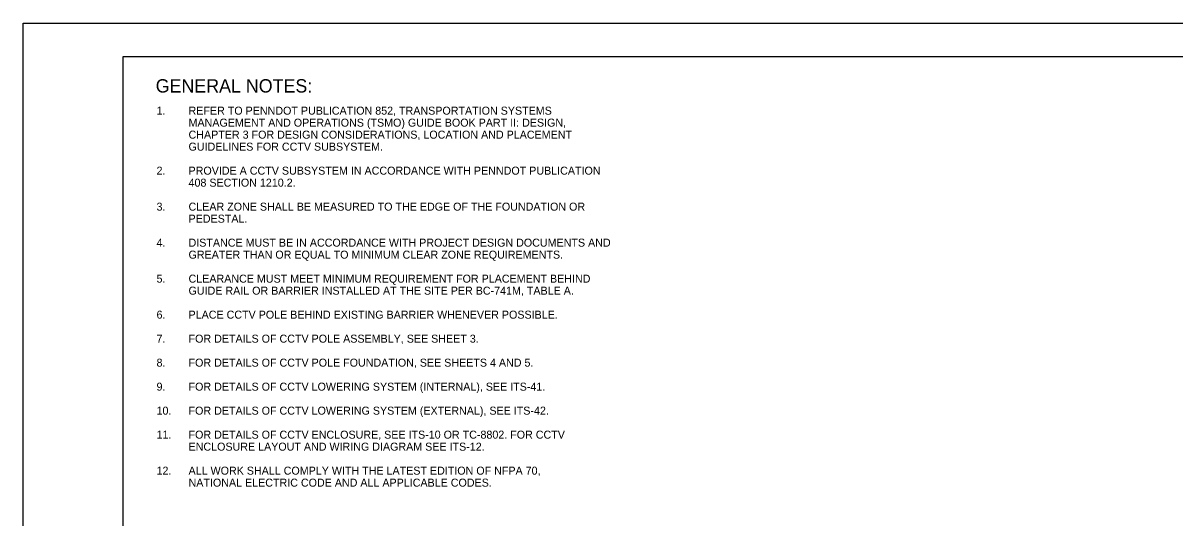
# Model space of a CAD drawing. Extents: x 1299104.8 to 1299141.6, y 239639.8 to 239661.8.
# Drawn here: x 1299104.8 to 1299122.08, y 239654.37 to 239661.79 of the extents above; entities that cross this region are included whole.
import ezdxf

# ---------------------------------------------------------------- set-up
doc = ezdxf.new("R2010")
doc.units = 0
for name, color, linetype in [('DIM TXT', 7, 'Continuous'), ('GS_plotshape_p', 7, 'Continuous'), ('Level 1', 7, 'Continuous')]:
    doc.layers.add(name, color=color, linetype=linetype)

msp = doc.modelspace()

# ---------------------------------------------------------------- linework, layer by layer
at = {"layer": 'DIM TXT'}
msp.add_line((1299104.802, 239661.791), (1299104.802, 239661.791), dxfattribs=at)
at = {"layer": 'GS_plotshape_p'}
msp.add_lwpolyline([(1299104.802, 239661.791), (1299138.802, 239661.791), (1299138.802, 239639.791), (1299104.802, 239639.791)], close=True, dxfattribs=at)
at = {"layer": 'Level 1'}
msp.add_lwpolyline([(1299138.302, 239640.291), (1299106.302, 239640.291), (1299106.302, 239661.291), (1299138.302, 239661.291)], close=True, dxfattribs=at)

# ---------------------------------------------------------------- texts
at = {"layer": 'DIM TXT'}
for s, height, p in [('GENERAL NOTES:', 0.2, (1299106.791, 239660.749)), ('1.', 0.12, (1299106.804, 239660.417)), ('REFER TO PENNDOT PUBLICATION 852, TRANSPORTATION SYSTEMS ', 0.12, (1299107.284, 239660.417)), ('MANAGEMENT AND OPERATIONS (TSMO) GUIDE BOOK PART II: DESIGN, ', 0.12, (1299107.284, 239660.237)), ('CHAPTER 3 FOR DESIGN CONSIDERATIONS, LOCATION AND PLACEMENT ', 0.12, (1299107.284, 239660.057)), ('GUIDELINES FOR CCTV SUBSYSTEM.', 0.12, (1299107.284, 239659.877)), ('2.', 0.12, (1299106.804, 239659.517)), ('PROVIDE A CCTV SUBSYSTEM IN ACCORDANCE WITH PENNDOT PUBLICATION ', 0.12, (1299107.284, 239659.517)), ('408 SECTION 1210.2.', 0.12, (1299107.284, 239659.337)), ('3.', 0.12, (1299106.804, 239658.977)), ('CLEAR ZONE SHALL BE MEASURED TO THE EDGE OF THE FOUNDATION OR ', 0.12, (1299107.284, 239658.977)), ('PEDESTAL.', 0.12, (1299107.284, 239658.797)), ('DISTANCE MUST BE IN ACCORDANCE WITH PROJECT DESIGN DOCUMENTS AND ', 0.12, (1299107.284, 239658.437)), ('4.', 0.12, (1299106.804, 239658.437)), ('GREATER THAN OR EQUAL TO MINIMUM CLEAR ZONE REQUIREMENTS.', 0.12, (1299107.284, 239658.257)), ('5.', 0.12, (1299106.804, 239657.897)), ('CLEARANCE MUST MEET MINIMUM REQUIREMENT FOR PLACEMENT BEHIND ', 0.12, (1299107.284, 239657.897)), ('GUIDE RAIL OR BARRIER INSTALLED AT THE SITE PER BC-741M, TABLE A.', 0.12, (1299107.284, 239657.717)), ('6.', 0.12, (1299106.804, 239657.357)), ('PLACE CCTV POLE BEHIND EXISTING BARRIER WHENEVER POSSIBLE.', 0.12, (1299107.284, 239657.357)), ('7.', 0.12, (1299106.804, 239656.997)), ('FOR DETAILS OF CCTV POLE ASSEMBLY, SEE SHEET 3.', 0.12, (1299107.284, 239656.997)), ('8.', 0.12, (1299106.804, 239656.637)), ('FOR DETAILS OF CCTV POLE FOUNDATION, SEE SHEETS 4 AND 5.', 0.12, (1299107.284, 239656.637)), ('9.', 0.12, (1299106.804, 239656.277)), ('FOR DETAILS OF CCTV LOWERING SYSTEM (INTERNAL), SEE ITS-41.', 0.12, (1299107.284, 239656.277)), ('10.', 0.12, (1299106.804, 239655.917)), ('FOR DETAILS OF CCTV LOWERING SYSTEM (EXTERNAL), SEE ITS-42.', 0.12, (1299107.284, 239655.917)), ('11.', 0.12, (1299106.804, 239655.557)), ('FOR DETAILS OF CCTV ENCLOSURE, SEE ITS-10 OR TC-8802. FOR CCTV ', 0.12, (1299107.284, 239655.557)), ('ENCLOSURE LAYOUT AND WIRING DIAGRAM SEE ITS-12.', 0.12, (1299107.284, 239655.377)), ('12.', 0.12, (1299106.804, 239655.017)), ('ALL WORK SHALL COMPLY WITH THE LATEST EDITION OF NFPA 70, ', 0.12, (1299107.284, 239655.017)), ('NATIONAL ELECTRIC CODE AND ALL APPLICABLE CODES.', 0.12, (1299107.284, 239654.837))]:
    msp.add_text(s, height=height, dxfattribs=at).set_placement(p)

doc.saveas('drawing.dxf')
